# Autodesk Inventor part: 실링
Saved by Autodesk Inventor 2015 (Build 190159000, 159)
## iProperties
Created: 2024-12
Part Number: 실링
Material: 일반
Document SubType Name: Modeling
Designer: 102-5
Density: 1 g/cm^3
Appearance: 기본값
Author: 102-5
Author: jhkim
Creation Date: 2024-11-28
Sending System: Autodesk Inventor 2025
Preprocessor: ST-DEVELOPER v20
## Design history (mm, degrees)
node "실링1"
node "솔리드1"
node "기준1"
